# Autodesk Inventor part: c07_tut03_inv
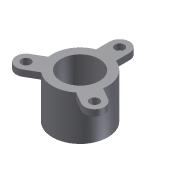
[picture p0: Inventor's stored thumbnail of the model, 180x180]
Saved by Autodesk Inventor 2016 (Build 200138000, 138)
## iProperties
Created: 2010-03
Part Number: c07_tut03_inv
Document SubType Name: Modeling
Designer: CADSoft
Density: 1 g/cm^3
Material: Generic
Appearance: Default
Author: CADSoft
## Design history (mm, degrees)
sketch "Sketch1"
  geometry: C1 r 97 at (0, 0); C2 r 140 at (0, 0); 1 further point
  constraints: 2 centre point, 2 coincident
  dimensions: "d0" = 194 diameter of C1; "d1" = 280 diameter of C2
extrude "Extrusion1" new body sketch "Sketch1" stored distance "d2" = 225; taper "d3" = 0 deg
pattern_circular "Circular Pattern2" dims angle "d38" = 360 deg
body "Solid1"
sketch "Sketch5"
  geometry: L1 (-50, 200)-(-50, 130.767); L2 (50, 200)-(50, 130.767); L3 (0, 0)-(0, 306.095); C1 r 97 at (0, 0) reference; C2 r 23.5 at (0, 200); A1 r 140 centre (0, 0) between (-50, 130.767) and (50, 130.767) reference; A2 r 50 centre (0, 200) between (50, 200) and (-50, 200); A3 r 140 centre (0, 0) between (50, 130.767) and (-50, 130.767)
  constraints: 7 point on circle, 6 end point, 3 centre point, 2 coincident, 2 tangent, 1 other
  dimensions: "d32" = 200 distance of A2.centre C1.centre; "d33" = 50 radius of A2; "d34" = 47 diameter of C2
extrude "Extrusion2" join sketch "Sketch5" distance "d35" = 32; taper "d36" = 0 deg
